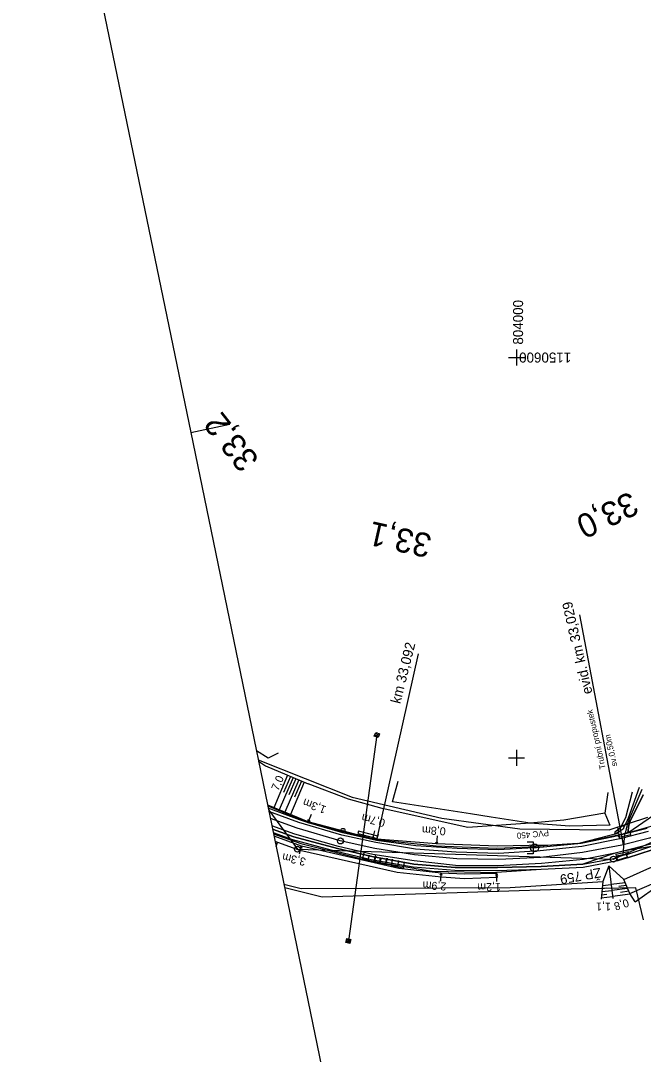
# Model space of a CAD drawing. Extents: x -804166 to -803706, y -1151030 to -1150147.
# Drawn here: x -804123.8 to -803968.4, y -1150774.1 to -1150515.9 of the extents above; entities that cross this region are included whole.
import ezdxf

# ---------------------------------------------------------------- set-up
doc = ezdxf.new("R2010")
doc.units = 0
for name, color, linetype in [('0381KM032-037P - Vrstva 1', 7, 'Continuous'), ('0381KM032-037P - Vrstva 11', 7, 'Continuous'), ('0381KM032-037P - Vrstva 13', 7, 'Continuous'), ('0381KM032-037P - Vrstva 16', 7, 'Continuous'), ('0381KM032-037P - Vrstva 17', 7, 'Continuous'), ('0381KM032-037P - Vrstva 19', 7, 'Continuous'), ('0381KM032-037P - Vrstva 25', 7, 'Continuous'), ('0381KM032-037P - Vrstva 4', 7, 'Continuous'), ('0381KM032-037P - Vrstva 43', 7, 'Continuous'), ('0381KM032-037P - Vrstva 44', 7, 'Continuous'), ('0381KM032-037P - Vrstva 48', 7, 'Continuous'), ('0381KM032-037P - Vrstva 49', 7, 'Continuous'), ('0381KM032-037P - Vrstva 7', 7, 'Continuous'), ('0381KM032-037P - Vrstva 9', 7, 'Continuous'), ('formát', 7, 'Continuous'), ('hran DP - hran DP', 7, 'Continuous'), ('krizky_1000 - souradnice', 7, 'Continuous'), ('krizky_1000 - Vrstva 1', 7, 'Continuous'), ('vyt_sit - polygon', 7, 'Continuous'), ('vyt_sit - stávající', 7, 'Continuous')]:
    doc.layers.add(name, color=color, linetype=linetype)

msp = doc.modelspace()

# ---------------------------------------------------------------- linework, layer by layer
at = {"layer": '0381KM032-037P - Vrstva 1'}
msp.add_lwpolyline([(-803901.91, -1150682.6), (-803910.01, -1150690), (-803918.64, -1150696.78), (-803928.04, -1150703.06), (-803937.95, -1150708.69), (-803946.8, -1150712.93), (-803956.66, -1150716.87), (-803966.85, -1150720.1), (-803973.69, -1150721.81), (-803983.51, -1150723.68), (-803993.92, -1150724.91), (-804004.46, -1150725.42), (-804014.95, -1150725.21), (-804025.47, -1150724.25), (-804035.41, -1150722.67), (-804044.08, -1150720.74), (-804054.77, -1150717.61), (-804061.47, -1150715.14)], dxfattribs=at)
at = {"layer": '0381KM032-037P - Vrstva 11'}
for p, q in [((-804034.26, -1150693.99), (-804035.54, -1150694.57)), ((-804034.75, -1150693.8), (-804035.36, -1150694.08)), ((-804034.44, -1150694.48), (-804035.04, -1150694.76)), ((-804041.41, -1150745.38), (-804042.6, -1150746.13)), ((-804041.93, -1150745.26), (-804042.49, -1150745.62)), ((-804041.53, -1150745.9), (-804042.08, -1150746.25))]:
    msp.add_line(p, q, dxfattribs=at)
for points in [[(-804034.6, -1150694.92), (-804035.54, -1150694.57), (-804035.19, -1150693.64), (-804034.25, -1150693.98)], [(-804041.63, -1150746.35), (-804042.61, -1150746.13), (-804042.39, -1150745.16), (-804041.41, -1150745.38)]]:
    msp.add_lwpolyline(points, close=True, dxfattribs=at)
at = {"layer": '0381KM032-037P - Vrstva 13'}
for p, q in [((-804051.27, -1150714.14), (-804052.03, -1150715.99)), ((-804035.82, -1150720.44), (-804051.93, -1150716.22)), ((-804035.5, -1150718.26), (-804035.97, -1150720.21)), ((-804019.87, -1150719.5), (-804020.03, -1150721.49)), ((-804054.2, -1150724.02), (-804053.75, -1150722.07)), ((-803974.7, -1150725.77), (-803974.91, -1150725)), ((-803972.34, -1150724.85), (-803974.74, -1150725.59)), ((-803974.74, -1150725.59), (-803974.7, -1150725.77)), ((-803972.29, -1150725.01), (-803974.7, -1150725.77)), ((-803972.54, -1150724.23), (-803972.54, -1150724.26)), ((-803972.54, -1150724.26), (-803972.29, -1150725.01)), ((-803972.34, -1150724.85), (-803972.29, -1150725.01)), ((-804018.95, -1150730.84), (-804018.83, -1150728.85)), ((-804004.99, -1150728.9), (-804004.87, -1150729.93)), ((-804004.95, -1150730.9), (-804004.99, -1150728.9))]:
    msp.add_line(p, q, dxfattribs=at)
for points in [[(-803902.54, -1150686.99), (-803908.53, -1150691.68), (-803917.54, -1150698.65), (-803926.89, -1150705.06), (-803937, -1150710.49), (-803946.02, -1150714.66), (-803956.26, -1150718.85), (-803966.29, -1150722.19), (-803972.54, -1150724.26)], [(-803972.29, -1150725.01), (-803966.12, -1150722.97), (-803955.96, -1150719.58), (-803945.71, -1150715.38), (-803936.57, -1150711.19), (-803926.51, -1150705.78), (-803917.07, -1150699.31), (-803908.04, -1150692.29), (-803902.09, -1150687.65)], [(-804052.03, -1150715.99), (-804062.15, -1150711.83)], [(-804062.12, -1150712.02), (-804052.3, -1150716.03), (-804051.93, -1150716.22)], [(-804060.92, -1150717.79), (-804055.61, -1150719.76), (-804044.75, -1150722.66), (-804036.16, -1150724.67), (-804025.7, -1150726.54), (-804015.38, -1150727.38), (-804004.78, -1150727.4), (-803993.85, -1150727.11), (-803983.42, -1150726.57), (-803974.91, -1150725)], [(-804052.11, -1150715.42), (-804052.03, -1150715.99), (-804051.56, -1150715.64)], [(-803991.2, -1150721.8), (-803996.89, -1150721.92), (-804004.84, -1150722.06), (-804020.03, -1150721.49), (-804035.97, -1150720.21), (-804052.03, -1150715.99)], [(-803974.7, -1150725.77), (-803983.37, -1150727.37), (-803993.84, -1150727.91), (-804005.29, -1150728.22), (-804015.43, -1150728.15), (-804025.86, -1150727.31), (-804036.32, -1150725.46), (-804045.02, -1150723.43), (-804055.91, -1150720.49), (-804060.73, -1150718.71)], [(-804060.69, -1150718.95), (-804053.9, -1150721.4), (-804036.64, -1150725.7), (-804021.1, -1150728.28), (-804004.99, -1150728.61), (-804004.87, -1150729.93)], [(-804004.99, -1150728.9), (-804013.04, -1150729.07), (-804018.83, -1150728.85), (-804029.4, -1150727.62), (-804053.75, -1150722.07), (-804060.56, -1150719.58)], [(-804036.15, -1150719.65), (-804035.97, -1150720.21), (-804035.56, -1150719.79)], [(-803991.2, -1150721.8), (-803997.06, -1150722.33), (-804004.97, -1150722.65), (-804020.12, -1150722.09), (-804035.82, -1150720.44)], [(-804004.87, -1150729.93), (-804012.98, -1150730.26), (-804018.76, -1150729.81), (-804029.79, -1150728.64), (-804054.15, -1150723.15), (-804060.27, -1150720.94)], [(-804053.57, -1150722.62), (-804053.75, -1150722.07), (-804054.16, -1150722.49)], [(-804020.29, -1150720.97), (-804020.03, -1150721.49), (-804019.69, -1150721.02)], [(-803974.74, -1150725.59), (-803974.75, -1150725.58), (-803974.86, -1150725.17), (-803974.86, -1150725.17), (-803974.91, -1150725)], [(-803972.34, -1150724.85), (-803972.34, -1150724.85), (-803972.48, -1150724.42), (-803972.48, -1150724.42), (-803972.54, -1150724.26), (-803972.54, -1150724.23)], [(-804018.56, -1150729.36), (-804018.83, -1150728.85), (-804019.16, -1150729.33)], [(-804004.68, -1150729.4), (-804004.99, -1150728.9), (-804005.28, -1150729.41)], [(-804004.99, -1150728.9), (-804004.99, -1150728.9), (-804004.99, -1150728.9), (-804004.99, -1150728.61)]]:
    msp.add_lwpolyline(points, dxfattribs=at)
at = {"layer": '0381KM032-037P - Vrstva 16'}
msp.add_line((-803972.81, -1150718.81), (-803972.25, -1150718.74), dxfattribs=at)
for points in [[(-803969.39, -1150707.42), (-803972.15, -1150715.07), (-803972.68, -1150716.27), (-803973.1, -1150717.09), (-803973.4, -1150717.86), (-803975.59, -1150719.16)], [(-803971.15, -1150708.54), (-803972.82, -1150714.95), (-803974.15, -1150717.57), (-803975.48, -1150718.61), (-803975.59, -1150719.16)], [(-803972.81, -1150718.81), (-803972.31, -1150716.69), (-803971.8, -1150715.26), (-803968.63, -1150707.87)], [(-803968.41, -1150709.25), (-803971.62, -1150715.84), (-803971.99, -1150716.8), (-803972.25, -1150718.74)]]:
    msp.add_lwpolyline(points, dxfattribs=at)
at = {"layer": '0381KM032-037P - Vrstva 17'}
for points in [[(-804059.54, -1150698.86), (-804062.04, -1150700.07), (-804064.95, -1150698.29)], [(-803996.63, -1150716.3), (-804006.34, -1150714.83), (-804011.55, -1150713.97), (-804030.97, -1150711.02), (-804029.61, -1150705.83)], [(-803977.22, -1150708.65), (-803977.99, -1150713.83)], [(-803977.99, -1150713.83), (-803976.74, -1150716.79), (-803986.83, -1150717.08), (-803996.63, -1150716.3)]]:
    msp.add_lwpolyline(points, dxfattribs=at)
at = {"layer": '0381KM032-037P - Vrstva 19'}
for p, q in [((-803973.32, -1150721.76), (-803984.23, -1150664.27)), ((-803971.53, -1150718.65), (-803974.65, -1150719.35)), ((-803974.65, -1150719.35), (-803974.64, -1150719.23)), ((-803974.51, -1150719.84), (-803974.65, -1150719.35)), ((-803974.51, -1150719.84), (-803971.47, -1150719.15)), ((-803973.09, -1150718.93), (-803973.51, -1150724.35)), ((-803972.25, -1150718.74), (-803972.81, -1150718.81)), ((-803971.47, -1150719.15), (-803971.53, -1150718.65)), ((-803975.23, -1150724.05), (-803972.11, -1150723.39)), ((-803975.23, -1150724.05), (-803975.1, -1150724.59)), ((-803972.01, -1150723.98), (-803975.1, -1150724.59)), ((-803974.91, -1150725), (-803975.1, -1150724.59)), ((-803974.91, -1150725), (-803974.9, -1150724.64)), ((-803974.91, -1150725), (-803974.91, -1150725)), ((-803972.11, -1150723.39), (-803972.01, -1150723.98))]:
    msp.add_line(p, q, dxfattribs=at)
for points in [[(-803974.64, -1150719.23), (-803973.09, -1150718.93), (-803972.81, -1150718.81)], [(-803975.1, -1150724.59), (-803974.9, -1150724.64), (-803973.51, -1150724.35), (-803972.67, -1150724.15), (-803972.01, -1150723.98)]]:
    msp.add_lwpolyline(points, dxfattribs=at)
for centre, major_axis, ratio, start_param, end_param in [((-803973.07, -1150718.94), (-0.255, -0.028), 0.056503, 4.768181, 7.86041), ((-803973.09, -1150718.94), (-0.255, -0.028), 0.056457, 1.624991, 4.720578), ((-803973.51, -1150724.33), (0.232, 0.091), 0.052847, 1.520766, 4.668999), ((-803973.51, -1150724.33), (0.232, 0.091), 0.052921, 4.661932, 7.811186)]:
    msp.add_ellipse(centre, major_axis=major_axis, ratio=ratio, start_param=start_param, end_param=end_param, dxfattribs=at)
at = {"layer": '0381KM032-037P - Vrstva 25'}
msp.add_line((-804034.9, -1150694.28), (-804042.01, -1150745.75), dxfattribs=at)
at = {"layer": '0381KM032-037P - Vrstva 4'}
msp.add_line((-803966.29, -1150722.19), (-803973.38, -1150723.34), dxfattribs=at)
for points in [[(-803967.41, -1150717.64), (-803975.82, -1150719.77), (-803983.88, -1150721.36), (-803994.18, -1150722.4), (-804004.64, -1150722.95), (-804014.86, -1150722.69), (-804025.14, -1150721.99), (-804034.98, -1150720.62), (-804043.41, -1150718.77), (-804051.93, -1150716.22), (-804054.24, -1150715.48), (-804062, -1150712.59)], [(-803967.18, -1150718.43), (-803974.22, -1150720.27), (-803983.73, -1150722.13), (-803994.13, -1150723.26), (-804004.52, -1150723.87), (-804015.05, -1150723.54), (-804025.27, -1150722.78), (-804035.17, -1150721.13), (-804043.67, -1150719.32), (-804054.39, -1150716.19), (-804061.83, -1150713.39)], [(-803966.45, -1150721.53), (-803973.38, -1150723.34), (-803975.35, -1150723.79), (-803983.32, -1150725.37), (-803993.82, -1150726.43), (-804004.8, -1150726.96), (-804015.29, -1150726.92), (-804025.6, -1150725.76), (-804035.88, -1150724.11), (-804044.5, -1150722.13), (-804055.4, -1150719.07), (-804061.09, -1150716.98)], [(-803975.35, -1150723.79), (-803983.42, -1150726.57), (-803993.85, -1150727.11), (-804004.78, -1150727.4), (-804015.38, -1150727.38), (-804025.7, -1150726.54), (-804036.16, -1150724.67), (-804044.75, -1150722.66), (-804055.61, -1150719.76), (-804060.92, -1150717.79)]]:
    msp.add_lwpolyline(points, dxfattribs=at)
at = {"layer": '0381KM032-037P - Vrstva 43'}
for points in [[(-803972.71, -1150719.94), (-803974.19, -1150720.21), (-803974.72, -1150717.26), (-803973.25, -1150716.99)], [(-803997.39, -1150721.01), (-803995.89, -1150721.01), (-803995.89, -1150724.01), (-803997.39, -1150724.01)], [(-804035.17, -1150724.55), (-804035.58, -1150726), (-804038.46, -1150725.19), (-804038.06, -1150723.74)], [(-804033.84, -1150725), (-804034.23, -1150726.45), (-804037.12, -1150725.67), (-804036.73, -1150724.22)], [(-804032.32, -1150725.04), (-804032.63, -1150726.51), (-804035.56, -1150725.9), (-804035.26, -1150724.43)], [(-804031.05, -1150725.35), (-804031.24, -1150726.84), (-804034.22, -1150726.45), (-804034.02, -1150724.96)], [(-804029.49, -1150725.62), (-804029.77, -1150727.09), (-804032.72, -1150726.52), (-804032.43, -1150725.05)], [(-804028.05, -1150726.05), (-804028.31, -1150727.53), (-804031.27, -1150727.01), (-804031.01, -1150725.53)]]:
    msp.add_lwpolyline(points, dxfattribs=at)
msp.add_circle((-803995.51, -1150722.5), 1, dxfattribs=at)
at = {"layer": '0381KM032-037P - Vrstva 44'}
msp.add_lwpolyline([(-803995.89, -1150722.51), (-803984.82, -1150721.44), (-803974.46, -1150718.74)], dxfattribs=at)
at = {"layer": '0381KM032-037P - Vrstva 48'}
for p, q in [((-804057.18, -1150704.34), (-804060.65, -1150712.45)), ((-804055.8, -1150704.93), (-804059.26, -1150713.02)), ((-804056.49, -1150704.63), (-804058.22, -1150708.69)), ((-804054.42, -1150705.52), (-804057.88, -1150713.59)), ((-804055.11, -1150705.22), (-804056.84, -1150709.27)), ((-804053.04, -1150706.11), (-804056.49, -1150714.16)), ((-804053.73, -1150705.81), (-804055.46, -1150709.84)), ((-804060.03, -1150722.14), (-804059.67, -1150721.16)), ((-803978.72, -1150733.42), (-803976.22, -1150733.11)), ((-803978.65, -1150732.65), (-803977.48, -1150732.51)), ((-803978.58, -1150731.89), (-803976.4, -1150731.62)), ((-803972.9, -1150731.19), (-803976.4, -1150731.62)), ((-803972.3, -1150732.62), (-803976.22, -1150733.11)), ((-803972.6, -1150731.91), (-803974.46, -1150732.13)), ((-803972, -1150733.34), (-803974.07, -1150733.6)), ((-803978.85, -1150734.94), (-803976.04, -1150734.6)), ((-803978.79, -1150734.18), (-803977.46, -1150734.02)), ((-803971.67, -1150734.06), (-803976.04, -1150734.6))]:
    msp.add_line(p, q, dxfattribs=at)
at = {"layer": '0381KM032-037P - Vrstva 49'}
for p, q in [((-803976.97, -1150726.99), (-803978.5, -1150730.91)), ((-803976.97, -1150726.99), (-803975.97, -1150735.13)), ((-803976.97, -1150726.99), (-803973.24, -1150730.36)), ((-804001.62, -1150732.39), (-803978.5, -1150730.91)), ((-803978.5, -1150730.91), (-803978.89, -1150735.31))]:
    msp.add_line(p, q, dxfattribs=at)
for points in [[(-803984.82, -1150721.44), (-803974.64, -1150719.23), (-803973.09, -1150718.93), (-803972.81, -1150718.81), (-803972.25, -1150718.74), (-803965.21, -1150716.75), (-803957.6, -1150714.53), (-803947.89, -1150710.4), (-803939.16, -1150706.21), (-803931.83, -1150702.12), (-803924.09, -1150697.22), (-803916.61, -1150691.84), (-803910.08, -1150686.51), (-803906.52, -1150683.39), (-803903.6, -1150681.32)], [(-803972.25, -1150718.74), (-803965.84, -1150714.34), (-803956.6, -1150711.22), (-803948.84, -1150707.73), (-803941.39, -1150704.08), (-803932.78, -1150700.06), (-803925.79, -1150694.95), (-803918.15, -1150689.68), (-803911.55, -1150684.9), (-803903.6, -1150681.32)], [(-803973.24, -1150730.36), (-803966.72, -1150727.46), (-803955.16, -1150723.59), (-803942.54, -1150718.42), (-803927.91, -1150711.46), (-803917.77, -1150704.05), (-803910.65, -1150697.21), (-803903.52, -1150690.49), (-803900.1, -1150686.57)], [(-803902.09, -1150687.65), (-803908.04, -1150692.29), (-803917.07, -1150699.31), (-803926.51, -1150705.78), (-803936.57, -1150711.19), (-803945.71, -1150715.38), (-803955.96, -1150719.58), (-803966.12, -1150722.97), (-803972.29, -1150725.01), (-803974.7, -1150725.77), (-803983.37, -1150727.37), (-803993.84, -1150727.91), (-804004.99, -1150728.61), (-804004.87, -1150729.93), (-804012.98, -1150730.26), (-804018.76, -1150729.81), (-804029.79, -1150728.64), (-804054.15, -1150723.15), (-804060.27, -1150720.94)], [(-803970.39, -1150735.93), (-803964.35, -1150731.61), (-803955.1, -1150727.23), (-803941.08, -1150721.95), (-803928.21, -1150715.68), (-803916.07, -1150708.06), (-803913.5, -1150704.53), (-803910.65, -1150697.21)], [(-804064.42, -1150700.87), (-804062.72, -1150701.97), (-804052.08, -1150706.52)], [(-803971.76, -1150733.92), (-803964.99, -1150730.97), (-803955.15, -1150726.85), (-803941.3, -1150721.62), (-803928.58, -1150715.41), (-803917.05, -1150707.62), (-803913.5, -1150704.53)], [(-803977.22, -1150708.65), (-803977.99, -1150713.83), (-803988.17, -1150715.55), (-803996.63, -1150716.3), (-804012.18, -1150717.41), (-804033.61, -1150712.69), (-804041.95, -1150710.32), (-804052.08, -1150706.52)], [(-803972.25, -1150718.74), (-803971.99, -1150716.8), (-803971.62, -1150715.84), (-803968.41, -1150709.25)], [(-804062.15, -1150711.83), (-804052.03, -1150715.99)], [(-803984.82, -1150721.44), (-803991.2, -1150721.8), (-803996.89, -1150721.92), (-804004.84, -1150722.06), (-804020.03, -1150721.49), (-804035.97, -1150720.21), (-804052.03, -1150715.99)], [(-803970.39, -1150735.93), (-803971.76, -1150733.92), (-803973.24, -1150730.36)], [(-804058.09, -1150731.52), (-804053.81, -1150732.63), (-804001.62, -1150732.39)]]:
    msp.add_lwpolyline(points, dxfattribs=at)
at = {"layer": '0381KM032-037P - Vrstva 7'}
msp.add_line((-804043.32, -1150718.13), (-804043.42, -1150718.1), dxfattribs=at)
for centre, radius in [((-804043.37, -1150718.12), 0.5), ((-804043.99, -1150720.76), 0.75)]:
    msp.add_circle(centre, radius, dxfattribs=at)
at = {"layer": '0381KM032-037P - Vrstva 9'}
for p, q in [((-804034.8, -1150720.15), (-804024.5, -1150674.02)), ((-804039.51, -1150718.34), (-804039.66, -1150718.92)), ((-804039.66, -1150718.92), (-804034.81, -1150720.14)), ((-804034.66, -1150719.56), (-804039.51, -1150718.34)), ((-804034.81, -1150720.14), (-804034.66, -1150719.56)), ((-804034.66, -1150719.56), (-804034.52, -1150718.98))]:
    msp.add_line(p, q, dxfattribs=at)
at = {"layer": 'formát'}
for p, q in [((-804123.84, -1150413.06), (-804081.38, -1150618.72)), ((-804081.38, -1150618.72), (-804071.58, -1150616.7)), ((-804081.38, -1150618.72), (-803996.46, -1151030.05))]:
    msp.add_line(p, q, dxfattribs=at)
at = {"layer": 'hran DP - hran DP'}
for p, q in [((-804064.5, -1150700.47), (-804041.05, -1150709.83)), ((-804041.05, -1150709.83), (-804018.63, -1150715.09)), ((-804018.63, -1150715.09), (-803999.22, -1150717.72)), ((-803976.9, -1150717.98), (-803967.26, -1150714.81)), ((-803999.22, -1150717.72), (-803976.9, -1150717.98)), ((-804048.58, -1150734.81), (-804057.89, -1150732.49)), ((-803986.36, -1150732.8), (-804048.58, -1150734.81)), ((-803982.91, -1150732.74), (-803986.36, -1150732.8)), ((-803970.22, -1150732.49), (-803982.91, -1150732.74)), ((-803968.3, -1150740.45), (-803970.22, -1150732.49))]:
    msp.add_line(p, q, dxfattribs=at)
at = {"layer": 'krizky_1000 - Vrstva 1'}
for points in [[(-804000, -1150598), (-804000, -1150602)], [(-804002, -1150600), (-803998, -1150600)], [(-804000, -1150698), (-804000, -1150702)], [(-804002, -1150700), (-803998, -1150700)]]:
    msp.add_lwpolyline(points, dxfattribs=at)
at = {"layer": 'vyt_sit - polygon'}
for p, q in [((-803975.82, -1150725.31), (-803907.43, -1150695.07)), ((-804061.9, -1150713.04), (-804054.72, -1150722.82)), ((-804054.72, -1150722.82), (-803975.82, -1150725.31))]:
    msp.add_line(p, q, dxfattribs=at)
at = {"layer": 'vyt_sit - stávající'}
for p, q in [((-804054.77, -1150722.82), (-804054.67, -1150722.82)), ((-803975.87, -1150725.31), (-803975.77, -1150725.31))]:
    msp.add_line(p, q, dxfattribs=at)
for centre in [(-804054.72, -1150722.82), (-803975.82, -1150725.31)]:
    msp.add_circle(centre, 0.756, dxfattribs=at)

# ---------------------------------------------------------------- texts
at = {"layer": '0381KM032-037P - Vrstva 13'}
for s, rotation, p in [('1,3m', 159.4135, (-804047.36, -1150712.19)), ('0,7m', 165.6438, (-804032.66, -1150715.41)), ('0,8m', 176.7126, (-804017.65, -1150717.4)), ('3,3m', 167.1636, (-804052.49, -1150725.09)), ('2,9m', 176.4791, (-804017.48, -1150731.17)), ('1,2m', 181.2027, (-804003.91, -1150731.23))]:
    msp.add_text(s, height=2, rotation=rotation, dxfattribs=at).set_placement(p)
at = {"layer": '0381KM032-037P - Vrstva 19'}
for s, height, p in [('evid. km 33,029', 2.5, (-803981.04, -1150683.82)), ('Trubní propustek', 1.5, (-803977.75, -1150702.64)), ('sv.0,50m', 1.5, (-803974.83, -1150701.98))]:
    msp.add_text(s, height=height, rotation=102.69, dxfattribs=at).set_placement(p)
at = {"layer": '0381KM032-037P - Vrstva 43'}
msp.add_text('PVC 450', height=1.5, rotation=185, dxfattribs=at).set_placement((-803991.99, -1150718.03))
at = {"layer": '0381KM032-037P - Vrstva 48'}
for s, rotation, p in [('7,0', 66.8248, (-804059.51, -1150708.39)), ('1,1', 179.9545, (-803976.45, -1150736.17)), ('0,8', 197.0064, (-803972.32, -1150735.18))]:
    msp.add_text(s, height=2, rotation=rotation, dxfattribs=at).set_placement(p)
at = {"layer": '0381KM032-037P - Vrstva 7'}
for s, rotation, p in [('33,2', 128.139, (-804064.09, -1150625.46)), ('33,0', 205.6225, (-803971.56, -1150633.32)), ('33,1', 167.4012, (-804020.85, -1150644.28))]:
    msp.add_text(s, height=6, rotation=rotation, dxfattribs=at).set_placement(p)
at = {"layer": '0381KM032-037P - Vrstva 9'}
msp.add_text('km 33,092', height=2.5, rotation=75.8763, dxfattribs=at).set_placement((-804029.06, -1150686.64))
at = {"layer": 'krizky_1000 - souradnice'}
for s, rotation, p in [('804000', 90, (-803998.38, -1150596.79)), ('1150600', 180, (-803986.36, -1150598.77))]:
    msp.add_text(s, height=2.5, rotation=rotation, dxfattribs=at).set_placement(p)
at = {"layer": 'vyt_sit - stávající'}
msp.add_text('ŽP 759', height=2.4, rotation=190, dxfattribs=at).set_placement((-803979.13, -1150727.45))

doc.saveas('drawing.dxf')
